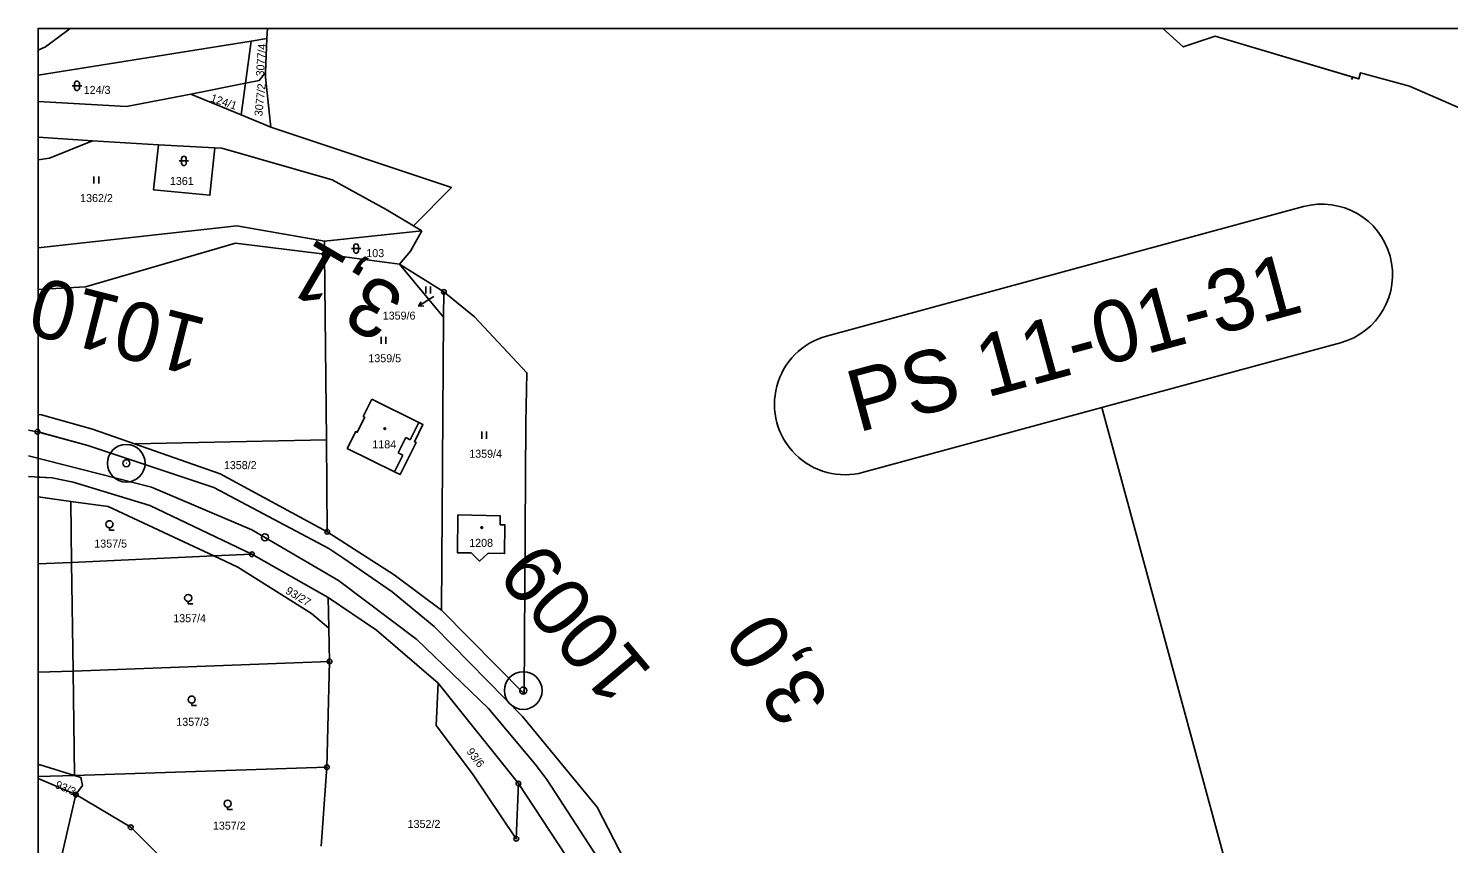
# Model space of a CAD drawing. Extents: x -728802 to -728097, y -1073200 to -1072700.
# Drawn here: x -728802.1 to -728500.3, y -1072873.2 to -1072700 of the extents above; entities that cross this region are included whole.
import ezdxf

# ---------------------------------------------------------------- set-up
doc = ezdxf.new("R2010")
doc.units = 0
for name, color, linetype in [('A5_JŽM', 7, 'Continuous'), ('body_ZBP', 7, 'Continuous'), ('Hranice parcel', 7, 'Continuous'), ('K_31_listy_JŽM', 7, 'Continuous'), ('Pop  PČ popisy', 7, 'Continuous'), ('ZZZ_popisky', 7, 'Continuous')]:
    doc.layers.add(name, color=color, linetype=linetype)

msp = doc.modelspace()

# ---------------------------------------------------------------- linework, layer by layer
at = {"layer": 'A5_JŽM'}
msp.add_line((-728800.21, -1072785.71), (-728800.11, -1072785.71), dxfattribs=at)
for points in [[(-728802.06, -1072785.37), (-728800.16, -1072785.71), (-728789.42, -1072788.62), (-728762.66, -1072797.6), (-728738.25, -1072810.52), (-728735.02, -1072812.66), (-728724.75, -1072819.77), (-728715.84, -1072827.08), (-728697.08, -1072846.24), (-728681.24, -1072865.51), (-728664.64, -1072897.67)], [(-728738.72, -1072787.42), (-728738.57, -1072806.97), (-728761.33, -1072794.7), (-728779.52, -1072788.29), (-728738.72, -1072787.42)], [(-728681.25, -1072876.02), (-728691.89, -1072859.66), (-728694.38, -1072856.37), (-728704.33, -1072844.56), (-728719.55, -1072829.89), (-728736.19, -1072817.3), (-728754.56, -1072806.55), (-728775.91, -1072797.5), (-728802.06, -1072790.86)], [(-728686.27, -1072878.28), (-728697.93, -1072860.51), (-728715.01, -1072839.18), (-728728.13, -1072827.9), (-728738.36, -1072820.92), (-728754.56, -1072811.75), (-728776.23, -1072801.43), (-728792.53, -1072796.44), (-728797, -1072795.53), (-728802.06, -1072795.25)]]:
    msp.add_lwpolyline(points, dxfattribs=at)
for centre, radius in [((-728800.16, -1072785.71), 0.499), ((-728751.8, -1072808.16), 0.75)]:
    msp.add_circle(centre, radius, dxfattribs=at)
at = {"layer": 'body_ZBP'}
for p, q in [((-728781.21, -1072792.43), (-728781.31, -1072792.41)), ((-728696.89, -1072840.77), (-728696.95, -1072840.69))]:
    msp.add_line(p, q, dxfattribs=at)
for centre, radius in [((-728781.26, -1072792.42), 4), ((-728781.26, -1072792.42), 0.756), ((-728696.92, -1072840.73), 4), ((-728696.92, -1072840.73), 0.756)]:
    msp.add_circle(centre, radius, dxfattribs=at)
at = {"layer": 'Hranice parcel'}
for p, q in [((-728755.94, -1072711.65), (-728754.72, -1072702.69)), ((-728754.72, -1072702.69), (-728751.37, -1072702.15)), ((-728751.65, -1072709.4), (-728751.37, -1072702.15)), ((-728520.64, -1072710.38), (-728549.87, -1072701.63)), ((-728792.24, -1072711.71), (-728792.24, -1072712.71)), ((-728791.24, -1072712.71), (-728791.24, -1072711.71)), ((-728755.94, -1072711.65), (-728767.56, -1072713.97)), ((-728755.94, -1072711.65), (-728756.85, -1072718.36)), ((-728520.64, -1072710.38), (-728520.93, -1072710.83)), ((-728519.4, -1072710.73), (-728520.64, -1072710.38)), ((-728792.74, -1072712.21), (-728790.74, -1072712.21)), ((-728756.85, -1072718.36), (-728767.56, -1072713.97)), ((-728750.53, -1072720.96), (-728756.85, -1072718.36)), ((-728788.43, -1072723.93), (-728800, -1072723.11)), ((-728788.43, -1072723.93), (-728774.4, -1072724.71)), ((-728762.43, -1072725.38), (-728774.4, -1072724.71)), ((-728770.01, -1072728.17), (-728768.01, -1072728.17)), ((-728769.51, -1072727.67), (-728769.51, -1072728.67)), ((-728768.51, -1072728.67), (-728768.51, -1072727.67)), ((-728788.13, -1072732.96), (-728788.13, -1072731.46)), ((-728787.13, -1072732.96), (-728787.13, -1072731.46)), ((-728718.45, -1072743.01), (-728739.17, -1072745.2)), ((-728718.45, -1072743.01), (-728720.26, -1072741.97)), ((-728739.14, -1072748.01), (-728739.17, -1072745.2)), ((-728733.43, -1072746.8), (-728731.43, -1072746.8)), ((-728732.93, -1072746.3), (-728732.93, -1072747.3)), ((-728731.93, -1072747.3), (-728731.93, -1072746.3)), ((-728738.72, -1072787.42), (-728739.14, -1072748.01)), ((-728723.23, -1072750.14), (-728739.14, -1072748.01)), ((-728713.83, -1072761.38), (-728723.23, -1072750.14)), ((-728713.79, -1072756.01), (-728723.23, -1072750.14)), ((-728717.64, -1072756.34), (-728717.64, -1072754.84)), ((-728716.64, -1072756.34), (-728716.64, -1072754.84)), ((-728713.79, -1072756.01), (-728713.83, -1072761.38)), ((-728713.83, -1072761.38), (-728714.27, -1072823.67)), ((-728727.09, -1072767.03), (-728727.09, -1072765.53)), ((-728726.09, -1072767.03), (-728726.09, -1072765.53)), ((-728719.07, -1072783.77), (-728720.91, -1072787.45)), ((-728800, -1072785.24), (-728800, -1072786.18)), ((-728721.88, -1072786.97), (-728723.48, -1072790.19)), ((-728720.91, -1072787.45), (-728721.88, -1072786.97)), ((-728705.72, -1072787.2), (-728705.72, -1072785.7)), ((-728704.72, -1072787.2), (-728704.72, -1072785.7)), ((-728738.72, -1072787.42), (-728779.52, -1072788.29)), ((-728738.57, -1072806.97), (-728738.72, -1072787.42)), ((-728723.48, -1072790.19), (-728722.51, -1072790.67)), ((-728722.51, -1072790.67), (-728724.29, -1072794.25)), ((-728792.9, -1072813.48), (-728793.08, -1072800.51)), ((-728784.84, -1072806.12), (-728784.84, -1072806.62)), ((-728784.84, -1072806.62), (-728783.84, -1072806.62)), ((-728762.69, -1072812.12), (-728792.9, -1072813.48)), ((-728792.58, -1072836.57), (-728792.9, -1072813.48)), ((-728762.69, -1072812.12), (-728754.56, -1072811.75)), ((-728754.56, -1072811.75), (-728738.36, -1072820.92)), ((-728768.11, -1072821.8), (-728768.11, -1072822.3)), ((-728768.11, -1072822.3), (-728767.11, -1072822.3)), ((-728738.36, -1072820.92), (-728738.22, -1072827.45)), ((-728738.22, -1072827.45), (-728738.07, -1072834.52)), ((-728738.07, -1072834.52), (-728792.58, -1072836.57)), ((-728738.07, -1072834.52), (-728738.63, -1072857.02)), ((-728792.27, -1072858.75), (-728792.58, -1072836.57)), ((-728715.01, -1072839.18), (-728697.93, -1072860.51)), ((-728767.36, -1072843.39), (-728767.36, -1072843.89)), ((-728767.36, -1072843.89), (-728766.36, -1072843.89)), ((-728792.27, -1072858.75), (-728800, -1072859)), ((-728800, -1072859.41), (-728791.98, -1072862.85)), ((-728738.63, -1072857.02), (-728792.27, -1072858.75)), ((-728738.63, -1072857.02), (-728739.84, -1072873.79)), ((-728686.27, -1072878.28), (-728697.93, -1072860.51)), ((-728797.74, -1072887.7), (-728791.98, -1072862.85)), ((-728759.73, -1072865.51), (-728759.73, -1072866.01)), ((-728759.73, -1072866.01), (-728758.73, -1072866.01))]:
    msp.add_line(p, q, dxfattribs=at)
for points in [[(-728800, -1072704.61), (-728798.41, -1072703.9), (-728793.19, -1072700)], [(-728800, -1072709.97), (-728754.72, -1072702.69)], [(-728751.37, -1072702.15), (-728751.23, -1072700)], [(-728560.99, -1072700), (-728556.68, -1072703.94), (-728549.87, -1072701.63), (-728519.4, -1072710.73), (-728519.03, -1072709.42), (-728508.64, -1072712.27), (-728490.92, -1072719.99), (-728470.17, -1072725.55), (-728454.65, -1072730.81), (-728452.72, -1072731.42), (-728444.29, -1072733.58), (-728414.4, -1072741.24), (-728374.54, -1072750.66), (-728337.07, -1072757.11)], [(-728751.65, -1072709.4), (-728753, -1072711.06), (-728755.94, -1072711.65)], [(-728750.53, -1072720.96), (-728750.89, -1072717.76), (-728751.69, -1072710.38), (-728751.65, -1072709.4)], [(-728767.56, -1072713.97), (-728781.19, -1072716.57), (-728800, -1072715.57)], [(-728720.26, -1072741.97), (-728712.18, -1072733.81), (-728750.53, -1072720.96)], [(-728800, -1072727.93), (-728797.56, -1072727.56), (-728788.43, -1072723.93)], [(-728774.4, -1072724.71), (-728775.48, -1072734.34), (-728763.5, -1072735.46), (-728762.43, -1072725.38)], [(-728762.43, -1072725.38), (-728760.96, -1072725.46), (-728737.53, -1072732.17), (-728726.07, -1072738.51), (-728720.26, -1072741.97)], [(-728739.17, -1072745.2), (-728757.75, -1072741.99), (-728800, -1072746.64)], [(-728723.23, -1072750.14), (-728720.88, -1072747.32), (-728718.45, -1072743.01)], [(-728739.14, -1072748.01), (-728758.03, -1072745.65), (-728789.9, -1072754.92), (-728800, -1072755.47)], [(-728714.27, -1072823.67), (-728696.72, -1072841.45), (-728696.37, -1072783.83), (-728696.13, -1072773.18), (-728707.27, -1072761.27), (-728713.79, -1072756.01)], [(-728729.07, -1072778.78), (-728719.07, -1072783.77), (-728718.22, -1072784.19), (-728720.03, -1072787.83), (-728719.7, -1072787.99), (-728723.09, -1072794.83), (-728724.29, -1072794.25), (-728734.3, -1072789.26), (-728732.51, -1072785.67), (-728732.18, -1072785.84), (-728730.59, -1072782.64), (-728730.92, -1072782.48), (-728729.07, -1072778.78)], [(-728800, -1072782.04), (-728799.31, -1072782.16), (-728788.43, -1072785.15), (-728779.52, -1072788.29)], [(-728509.9, -1073046.86), (-728508.93, -1073042.5), (-728513.22, -1073039.89), (-728513.66, -1073035.13), (-728514.64, -1073029.26), (-728515.01, -1073025.35), (-728515.38, -1073021.39), (-728541.24, -1073024.99), (-728556.03, -1073020.59), (-728582.13, -1073004.22), (-728604.14, -1072988.92), (-728619.81, -1072972.56), (-728640.48, -1072947.72), (-728648.31, -1072932.44), (-728664.64, -1072897.67), (-728681.24, -1072865.51), (-728697.08, -1072846.24), (-728715.84, -1072827.08), (-728724.75, -1072819.77), (-728735.02, -1072812.66), (-728738.25, -1072810.52), (-728762.66, -1072797.6), (-728789.42, -1072788.62), (-728800, -1072785.75)], [(-728779.52, -1072788.29), (-728761.33, -1072794.7), (-728738.57, -1072806.97)], [(-728800, -1072795.36), (-728797, -1072795.53), (-728792.53, -1072796.44), (-728776.23, -1072801.43), (-728754.56, -1072811.75)], [(-728800, -1072799.55), (-728793.08, -1072800.51)], [(-728793.08, -1072800.51), (-728785.11, -1072801.61), (-728762.69, -1072812.12)], [(-728710.83, -1072803.41), (-728701.82, -1072803.6), (-728701.82, -1072805.47), (-728700.83, -1072805.51), (-728700.9, -1072811.6), (-728704.4, -1072811.54), (-728706.24, -1072813.21), (-728707.95, -1072811.47), (-728710.92, -1072811.43), (-728710.83, -1072803.41)], [(-728738.57, -1072806.97), (-728724.31, -1072816.16), (-728714.27, -1072823.67)], [(-728792.9, -1072813.48), (-728800, -1072813.79)], [(-728762.69, -1072812.12), (-728757.58, -1072814.51), (-728741.9, -1072824.35), (-728738.22, -1072827.45)], [(-728715.01, -1072839.18), (-728728.13, -1072827.9), (-728738.36, -1072820.92)], [(-728792.58, -1072836.57), (-728800, -1072836.85)], [(-728697.93, -1072860.51), (-728698.39, -1072872.21), (-728707.71, -1072858.43), (-728715.45, -1072848.15), (-728715.01, -1072839.18)], [(-728792.27, -1072858.75), (-728799.56, -1072856.52), (-728800, -1072856.53)], [(-728791.98, -1072862.85), (-728790.58, -1072860.93), (-728790.9, -1072859.17), (-728792.27, -1072858.75)], [(-728791.98, -1072862.85), (-728780.33, -1072869.76), (-728769.94, -1072880.13)]]:
    msp.add_lwpolyline(points, dxfattribs=at)
for centre, radius in [((-728739.14, -1072748.01), 0.5), ((-728739.14, -1072748.01), 0.0303), ((-728713.79, -1072756.01), 0.5), ((-728713.79, -1072756.01), 0.0303), ((-728726.33, -1072785.08), 0.175), ((-728784.84, -1072805.37), 0.75), ((-728738.57, -1072806.97), 0.5), ((-728738.57, -1072806.97), 0.0303), ((-728705.73, -1072806.08), 0.175), ((-728754.56, -1072811.75), 0.5), ((-728754.56, -1072811.75), 0.0303), ((-728768.11, -1072821.05), 0.75), ((-728738.07, -1072834.52), 0.5), ((-728738.07, -1072834.52), 0.0303), ((-728767.36, -1072842.64), 0.75), ((-728738.63, -1072857.02), 0.5), ((-728738.63, -1072857.02), 0.0303), ((-728791.98, -1072862.85), 0.5), ((-728697.93, -1072860.51), 0.5), ((-728697.93, -1072860.51), 0.0303), ((-728791.98, -1072862.85), 0.0303), ((-728759.73, -1072864.76), 0.75), ((-728780.33, -1072869.76), 0.5), ((-728780.33, -1072869.76), 0.0303), ((-728698.39, -1072872.21), 0.5), ((-728698.39, -1072872.21), 0.0303)]:
    msp.add_circle(centre, radius, dxfattribs=at)
for centre, start, end in [((-728791.74, -1072711.71), 0, 180), ((-728791.74, -1072712.71), 180, 359.9879), ((-728769.01, -1072727.67), 0, 180), ((-728769.01, -1072728.67), 180, 359.9879), ((-728732.43, -1072746.3), 0, 180), ((-728732.43, -1072747.3), 180, 359.9879), ((-728800.16, -1072785.71), 288.6629, 71.3371)]:
    msp.add_arc(centre, 0.5, start, end, dxfattribs=at)
at = {"layer": 'K_31_listy_JŽM'}
msp.add_lwpolyline([(-728800, -1073200), (-728800, -1072700), (-728100, -1072700), (-728100, -1073200), (-728800, -1073200)], dxfattribs=at)
at = {"layer": 'Pop  PČ popisy'}
for p, q in [((-728715.92, -1072756.97), (-728716.64, -1072757.43)), ((-728716.64, -1072757.43), (-728719.16, -1072759.06)), ((-728719.16, -1072759.06), (-728718.59, -1072758.1)), ((-728719.16, -1072759.06), (-728718.04, -1072758.94))]:
    msp.add_line(p, q, dxfattribs=at)
at = {"layer": 'ZZZ_popisky'}
for points in [[(-728632.48, -1072765.39), (-728531.15, -1072737.87)], [(-728523.28, -1072766.82), (-728573.95, -1072780.58)], [(-728504.21, -1073037.38), (-728573.95, -1072780.58), (-728624.61, -1072794.34)]]:
    msp.add_lwpolyline(points, dxfattribs=at)
for centre, start, end in [((-728527.21, -1072752.35), 285.1943, 105.1943), ((-728628.54, -1072779.87), 105.1943, 285.1943)]:
    msp.add_arc(centre, 15, start, end, dxfattribs=at)

# ---------------------------------------------------------------- texts
at = {"layer": 'A5_JŽM'}
for s, rotation, p in [('3,1', 149.6763, (-728721.51, -1072756.37)), ('3,0', 123.0351, (-728631.43, -1072842.57))]:
    msp.add_text(s, height=12.5, rotation=rotation, dxfattribs=at).set_placement(p)
at = {"layer": 'body_ZBP'}
for s, rotation, p in [('1010', 165.7406, (-728763.66, -1072761.84)), ('1009', 130.1205, (-728669.16, -1072836.75))]:
    msp.add_text(s, height=12.5, rotation=rotation, dxfattribs=at).set_placement(p)
at = {"layer": 'Hranice parcel'}
for s, rotation, p in [('3077/4', 86, (-728752.04, -1072710.26)), ('124/1', 341, (-728763.5, -1072715.48)), ('3077/2', 84, (-728752.37, -1072718.74)), ('93/27', 329, (-728747.57, -1072819.98)), ('93/6', 307, (-728709.06, -1072853.72)), ('93/3', 337, (-728796.51, -1072861.36))]:
    msp.add_text(s, height=1.7, rotation=rotation, dxfattribs=at).set_placement(p)
for s, p in [('124/3', (-728790.31, -1072713.92)), ('1361', (-728771.99, -1072733.28)), ('1362/2', (-728791.07, -1072736.91)), ('103', (-728730.26, -1072748.61)), ('1359/6', (-728726.77, -1072761.89)), ('1359/5', (-728729.82, -1072770.95)), ('1184', (-728728.98, -1072789.25)), ('1359/4', (-728708.39, -1072791.25)), ('1358/2', (-728760.53, -1072793.67)), ('1357/5', (-728788.06, -1072810.34)), ('1208', (-728708.4, -1072810.18)), ('1357/4', (-728771.28, -1072826.2)), ('1357/3', (-728770.64, -1072848.22)), ('1357/2', (-728762.86, -1072870.29)), ('1352/2', (-728721.48, -1072869.92))]:
    msp.add_text(s, height=1.7, dxfattribs=at).set_placement(p)
at = {"layer": 'ZZZ_popisky'}
msp.add_text('PS 11-01-31', height=13.125, rotation=15.1943, dxfattribs=at).set_placement((-728625.83, -1072785.93))

doc.saveas('drawing.dxf')
